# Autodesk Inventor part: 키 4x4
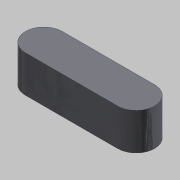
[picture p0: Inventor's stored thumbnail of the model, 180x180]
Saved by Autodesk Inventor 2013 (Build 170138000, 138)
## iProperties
Created: 2016-04
Part Number: 키 4x4
Document SubType Name: Modeling
Designer: mdu
Density: 7.86 g/cm^3
Mass: 1.65269 g
Surface Area: 2.35398 cm^2
Volume: 0.210265 cm^3
Material: 강철, 연강
Author: mdu
Revision Number: 1
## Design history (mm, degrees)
sketch "스케치1"
  geometry: L1 (-5, -2)-(5, -2); L2 (5, 2)-(-5, 2); A1 r 2 centre (5, 0) between (5, -2) and (5, 2); A2 r 2 centre (-5, 0) between (-5, 2) and (-5, -2); 2 further points
  constraints: 4 end point, 4 point on circle, 4 tangent, 2 centre point, 1 horizontal, 1 horizontal alignment, 1 midpoint, 1 parallel, 1 vertical alignment
  dimensions: "d0" = 4 distance between parallel lines of L1 L2; "d1" = 14 dimension on A1 A2
extrude "돌출1" new body sketch "스케치1" stored distance "d2" = 4; taper "d3" = 0 deg
node "솔리드1"
